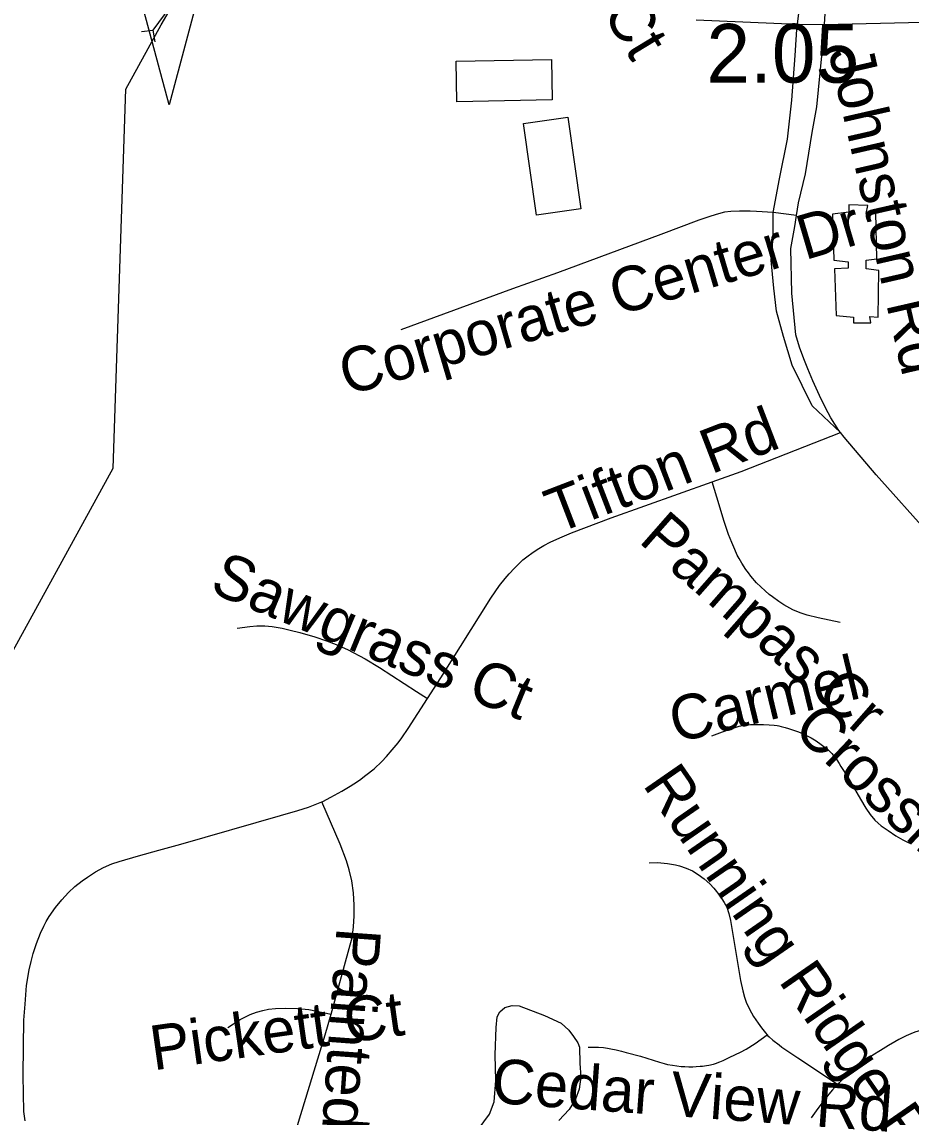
# Model space of a CAD drawing. Extents: x 1383679 to 1536984, y 460658 to 651027.
# Drawn here: x 1444051 to 1445945, y 489649 to 491982 of the extents above; entities that cross this region are included whole.
import ezdxf

# ---------------------------------------------------------------- set-up
doc = ezdxf.new("R2010")
doc.units = 0
for name, color, linetype in [('Exist Cultural Warehouse Building Footprint', 7, 'Continuous'), ('Exist Hydrographic Creek Single Shore', 7, 'Continuous'), ('Exist Road Non-System Type 51', 7, 'Continuous'), ('Exist Road Non-System Type 51 Label', 7, 'Continuous'), ('Exist Road Primary NC UnDivided 4 Lane Attributed', 7, 'Continuous'), ('Exist Road Secondary Mileage Hundredths English Label', 7, 'Continuous'), ('Exist Road Secondary Structure Culvert Attributed CELL', 7, 'Continuous'), ('Exist Road Secondary Structure Culvert CELL', 7, 'Continuous')]:
    doc.layers.add(name, color=color, linetype=linetype)

msp = doc.modelspace()

# ---------------------------------------------------------------- linework, layer by layer
at = {"layer": 'Exist Cultural Warehouse Building Footprint'}
for points in [[(1445178.6, 491902), (1445180.2, 491815.7), (1444977, 491811.9), (1444975.4, 491898.2), (1445178.6, 491902)], [(1445119.4, 491765.3), (1445213.5, 491778.6), (1445241, 491583.7), (1445146.9, 491570.4), (1445119.4, 491765.3)], [(1445812.4, 491592.2), (1445812.4, 491576.7), (1445777.2, 491572), (1445780.4, 491474.2), (1445810.8, 491471.1), (1445810.8, 491457.2), (1445782, 491455.6), (1445785.2, 491356.2), (1445822, 491353.1), (1445822, 491340.7), (1445858.8, 491340.7), (1445857.2, 491354.7), (1445874.8, 491353.1), (1445876.4, 491452.5), (1445849.2, 491455.6), (1445849.2, 491474.2), (1445871.6, 491477.3), (1445870, 491576.7), (1445849.2, 491573.6), (1445852.4, 491590.7), (1445812.4, 491592.2)]]:
    msp.add_lwpolyline(points, dxfattribs=at)
at = {"layer": 'Exist Hydrographic Creek Single Shore'}
msp.add_lwpolyline([(1443490.2, 489395.8), (1443517.3, 489946.6), (1443570.2, 490119.5), (1443673.2, 490275), (1443995.2, 490577.1), (1444245.2, 491031.6), (1444272.1, 491838.8), (1444347.5, 491975.6), (1444364.1, 492005), (1444375.6, 492029.3), (1444402.4, 492070.2), (1444764, 492263.2), (1445089, 492499.4), (1445408, 492730.5), (1445453.8, 492777.2), (1445478, 492822.8), (1445503.4, 492907.1), (1445567.9, 493066.2), (1445627.6, 493256.8)], dxfattribs=at)
at = {"layer": 'Exist Road Non-System Type 51'}
for p, q in [((1445705.3, 492000.5), (1445702.4, 491977.2)), ((1445761.2, 491999.8), (1445759.6, 491976.3)), ((1445697.8, 491910.3), (1445702.4, 491977.2)), ((1445759.6, 491976.3), (1445755, 491909.6)), ((1445700.7, 491569.7), (1445650.8, 491575.6))]:
    msp.add_line(p, q, dxfattribs=at)
for points in [[(1445650.8, 491575.6), (1445664.7, 491647.3), (1445681.5, 491732), (1445690.8, 491815), (1445697.8, 491910.3)], [(1445700.7, 491569.7), (1445704.7, 491596.8), (1445719.6, 491658.1), (1445734.4, 491746.5), (1445743.7, 491800.6), (1445755, 491909.6)], [(1445650.8, 491575.6), (1445615.3, 491578.2), (1445602.3, 491578.6), (1445579, 491579), (1445560.9, 491578.2), (1445547.1, 491576.3), (1445534.8, 491573.1), (1445518.3, 491568.4), (1445492.6, 491559.3), (1445411.5, 491528.7), (1445191.4, 491447.3), (1445096, 491413), (1444858.2, 491326.2)], [(1445794.3, 491107.2), (1445734.4, 491164.1), (1445691.7, 491250.7), (1445673.1, 491312), (1445658.2, 491366), (1445652.7, 491414.7), (1445647.1, 491474.2), (1445650.8, 491522.9), (1445650.8, 491575.6)], [(1445794.3, 491107.2), (1445791.2, 491111.4), (1445782.1, 491124.8), (1445774.2, 491138.4), (1445762.6, 491159.9), (1445749.6, 491186.1), (1445735.7, 491217.3), (1445724.7, 491243.2), (1445716.3, 491264.3), (1445707.3, 491289.1), (1445699.2, 491315.4), (1445690.8, 491403.9), (1445688.9, 491499.5), (1445697.3, 491546.3), (1445700.7, 491569.7)], [(1445521.2, 491002.2), (1445582.7, 491024), (1445794.3, 491107.2)], [(1446134.7, 490647.2), (1446134.6, 490647.5), (1446128.8, 490665.1), (1446118.9, 490689.6), (1446104.6, 490720.6), (1446086.1, 490755.1), (1446071.5, 490780), (1446053.8, 490807), (1446040.6, 490824.4), (1446025.6, 490843.6), (1445984.9, 490889.3), (1445870.7, 491016.9), (1445802, 491097.2), (1445794.3, 491107.2)], [(1444914.8, 490541), (1444942.9, 490584.9), (1445049.8, 490754.8), (1445058.8, 490767.9), (1445067.8, 490781.2), (1445079.8, 490796.6), (1445088.3, 490806.2), (1445099.8, 490818.4), (1445107.7, 490826.3), (1445118, 490835.9), (1445129, 490844.8), (1445137.1, 490850.6), (1445148.5, 490858.1), (1445162.5, 490866.7), (1445176.2, 490874), (1445196.6, 490883), (1445221.3, 490893.5), (1445305.9, 490925.9), (1445521.2, 491002.2)], [(1445793.9, 490703), (1445747.2, 490712.6), (1445723.6, 490718.1), (1445708.4, 490723.4), (1445693, 490729.9), (1445673.5, 490740.4), (1445662.8, 490747.7), (1445649.4, 490757.6), (1445642.7, 490762.6), (1445634.1, 490770), (1445615.7, 490787.3), (1445603.3, 490801.7), (1445598.2, 490808.2), (1445592.6, 490815.7), (1445584.5, 490828.9), (1445578.3, 490839.3), (1445574.6, 490846.4), (1445569.2, 490858.2), (1445562.7, 490873), (1445555.8, 490890.4), (1445545.9, 490919.6), (1445535.9, 490953.4), (1445521.2, 491002.2)], [(1444509.5, 490690.8), (1444536, 490694.4), (1444551.3, 490695.6), (1444568, 490695.6), (1444583.6, 490694.4), (1444605.2, 490690.5), (1444622, 490686.4), (1444643, 490681.1), (1444674.4, 490671.9), (1444699.8, 490663.4), (1444720.3, 490655.5), (1444744.4, 490645.2), (1444782.1, 490625.1), (1444812.6, 490606.8), (1444891, 490555.4), (1444914.8, 490541)], [(1444689.3, 490320.7), (1444691.4, 490321.5), (1444709.1, 490330.7), (1444732.4, 490343.3), (1444750.1, 490354), (1444758, 490358.9), (1444769.5, 490367), (1444783.3, 490377.2), (1444800.8, 490390.9), (1444817.2, 490406.8), (1444827, 490417.4), (1444839.7, 490431.2), (1444851.9, 490446.2), (1444859.8, 490457.2), (1444873.4, 490476.7), (1444914.8, 490541)], [(1445520.5, 490461.2), (1445543.4, 490469.5), (1445559.2, 490475.2), (1445569.9, 490479.1), (1445578.8, 490481.8), (1445589.9, 490483.8), (1445602.7, 490485.2), (1445616.5, 490485.7), (1445630.5, 490485.4), (1445642.2, 490484.9), (1445652.9, 490483.9), (1445659.4, 490483), (1445663.1, 490482.3), (1445667.8, 490481.3), (1445676.5, 490479), (1445684, 490477), (1445692.1, 490474.4), (1445702.8, 490470.7), (1445712, 490466.9), (1445719.5, 490463.5), (1445731.7, 490457.1), (1445742.4, 490450.8), (1445753.6, 490443.2), (1445766.9, 490432.6), (1445775.9, 490423.9), (1445781.1, 490417.5), (1445786.3, 490410.3), (1445791.5, 490402.2), (1445795.5, 490396.2), (1445807.6, 490377.1), (1445837.1, 490326.5), (1445848.5, 490307.4), (1445857.4, 490293.8), (1445867.3, 490282), (1445874.4, 490275.2), (1445881, 490269.7), (1445895.7, 490259.6), (1445912.4, 490248.6), (1445926.9, 490240), (1445935.6, 490235.4), (1445944.8, 490231.3)], [(1444057.7, 489641.6), (1444054.5, 489661.5), (1444053.1, 489738.2), (1444053.8, 489799.6), (1444055, 489855.8), (1444057.7, 489889.8), (1444060.6, 489929.4), (1444065.8, 489963.3), (1444070.3, 489980.6), (1444075, 489998), (1444081.9, 490018.9), (1444090.3, 490041.4), (1444097.2, 490056), (1444102.1, 490066.2), (1444108.4, 490076.7), (1444122.3, 490096), (1444135.8, 490112.2), (1444150.2, 490127.6), (1444163.7, 490140.1), (1444179, 490152.6), (1444190.2, 490160.5), (1444207.4, 490171.7), (1444224.6, 490181), (1444242, 490188.4), (1444257.5, 490193.9), (1444298.9, 490205.6), (1444342.6, 490217.7), (1444389, 490230.3), (1444601.4, 490291.3), (1444638.1, 490302.5), (1444661.1, 490309.7), (1444689.3, 490320.7)], [(1444709.2, 489868.5), (1444750.1, 490015.9), (1444754, 490031.2), (1444757, 490054.4), (1444758.7, 490077.8), (1444758.6, 490100.9), (1444757.2, 490126.9), (1444753.3, 490152.5), (1444747.9, 490175.6), (1444741.9, 490194.8), (1444728.4, 490230.4), (1444689.3, 490320.7)], [(1445386.8, 490191.1), (1445404.3, 490191.3), (1445425.9, 490189.2), (1445442.7, 490186.6), (1445451.6, 490184.5), (1445465.8, 490179.8), (1445479, 490174), (1445491.1, 490166.1), (1445504.2, 490156.7), (1445515.8, 490146.1), (1445524.7, 490137.2), (1445538.3, 490120.1), (1445546.8, 490106.7), (1445552.1, 490096.2), (1445556.3, 490083.1), (1445559.8, 490067.9), (1445578.3, 489957.4), (1445581.5, 489940.1), (1445586.2, 489918), (1445589.9, 489904.9), (1445593.6, 489894.4), (1445600.4, 489879.1), (1445609.4, 489863.9), (1445618.8, 489849.7), (1445626.3, 489839.5), (1445634.5, 489828.5), (1445638.3, 489824.2)], [(1446202.3, 489904.6), (1446058.2, 489861.3), (1445995.3, 489843.2), (1445982.8, 489839.4), (1445968.5, 489835.2), (1445959.8, 489832.4), (1445952.9, 489830), (1445944.1, 489826.5), (1445934.2, 489822.4), (1445925.7, 489818.1), (1445918.4, 489814.3), (1445910.4, 489809.8), (1445896.8, 489802.1), (1445879.5, 489791), (1445863, 489780.9), (1445848.2, 489770.3), (1445835.1, 489760.2), (1445820.2, 489748), (1445805.6, 489735.5), (1445798.9, 489729.6), (1445790, 489721), (1445788.4, 489719.3)], [(1444489.1, 489840.1), (1444515.9, 489857.1), (1444536.7, 489867.6), (1444550.4, 489872.7), (1444563.6, 489876.4), (1444575.8, 489879.1), (1444591.2, 489880.8), (1444612.2, 489881.3), (1444637.6, 489880.8), (1444661.6, 489878.6), (1444709.2, 489868.5)], [(1445010.8, 489606.3), (1445046.5, 489655.9), (1445056.6, 489682.2), (1445060.4, 489727.4), (1445058.9, 489782.3), (1445061.1, 489840.2), (1445063.4, 489862.8), (1445068.6, 489873.3), (1445079.2, 489883.1), (1445095, 489886.8), (1445110, 489886.1), (1445163.9, 489865.4), (1445199.1, 489849.6), (1445215.4, 489834.2), (1445225.8, 489821.2), (1445235.1, 489807.8), (1445238.6, 489798.5)], [(1444609.1, 489477.5), (1444608.8, 489479.5), (1444608.1, 489493.2), (1444608.8, 489508.6), (1444610.2, 489521.5), (1444612.7, 489535.6), (1444616.3, 489553.1), (1444621.4, 489572.9), (1444628.2, 489597.7), (1444640, 489638.2), (1444696.9, 489824.2), (1444709.2, 489868.5)], [(1445257.1, 489798.2), (1445268.1, 489798.6), (1445278.6, 489798.5), (1445289.4, 489797.3), (1445298.4, 489796), (1445305.1, 489794.9), (1445316.3, 489792.7), (1445328, 489789.9), (1445338.2, 489787.1), (1445368.6, 489778.8), (1445395.3, 489770.7), (1445409.2, 489766.4), (1445418.7, 489763.6), (1445426, 489761.7), (1445436.4, 489759.7), (1445445.9, 489758.2), (1445455.1, 489757.4), (1445462.9, 489756.9), (1445471.5, 489756.5), (1445479.7, 489756.5), (1445487, 489756.9), (1445495.4, 489757.6), (1445500.6, 489758), (1445509.2, 489759.3), (1445513.9, 489760), (1445523.7, 489762.3), (1445528.4, 489763.8), (1445537.6, 489767.1), (1445544.6, 489770.1), (1445559, 489776.8), (1445581.2, 489787.5), (1445593.3, 489794.2), (1445612.9, 489806.3), (1445638.3, 489824.2)], [(1445638.3, 489824.2), (1445639.6, 489822.7), (1445642.5, 489820), (1445650.5, 489813.4), (1445663.6, 489803.2), (1445669.8, 489798.5), (1445703.2, 489775.7), (1445788.4, 489719.3)], [(1445238.6, 489798.5), (1445239.4, 489763.5), (1445241.6, 489734.9), (1445237.9, 489708.6), (1445229.6, 489687.5), (1445216.1, 489665.8), (1445194.2, 489642.4)], [(1445788.4, 489719.3), (1445783.7, 489714.2), (1445777.4, 489707.4), (1445769.7, 489697.9), (1445765.3, 489692.5), (1445759.6, 489685.1), (1445746.3, 489667.6), (1445732.2, 489647.9)]]:
    msp.add_lwpolyline(points, dxfattribs=at)
at = {"layer": 'Exist Road Primary NC UnDivided 4 Lane Attributed'}
msp.add_lwpolyline([(1445486.9, 491986), (1445702.4, 491977.2), (1445759.6, 491976.3), (1445968.8, 491981), (1446235.2, 491975.4), (1446313.3, 491980.2), (1446364.2, 491977.5), (1446825.6, 491978), (1447208.6, 491971.6), (1447596.6, 491974.1), (1447846.7, 491976), (1448007.8, 491975.1)], dxfattribs=at)
at = {"layer": 'Exist Road Secondary Structure Culvert Attributed CELL'}
msp.add_lwpolyline([(1444467.6, 492191.4), (1444364.1, 491805), (1444260.6, 492191.4), (1444364.1, 492005)], close=True, dxfattribs=at)
at = {"layer": 'Exist Road Secondary Structure Culvert CELL'}
for p, q in [((1444330.3, 491964.5), (1444366.6, 492012.9)), ((1444305.1, 491961.5), (1444330.3, 491964.5)), ((1444334.6, 491939.4), (1444330.3, 491964.5))]:
    msp.add_line(p, q, dxfattribs=at)

# ---------------------------------------------------------------- texts
at = {"layer": 'Exist Road Non-System Type 51 Label'}
for s, rotation, p in [('Nellum Ct', 301.2703, (1445062.2, 492370.7)), ('Johnston Rd', 282.885, (1445768.6, 491918.9)), ('Corporate Center Dr', 16.4922, (1444743.5, 491185.4)), ('Tifton Rd', 21.0381, (1445189.3, 490891.1)), ('Pampas Cr', 318.7019, (1445362.1, 490874.8)), ('Sawgrass Ct', 337.5681, (1444447.6, 490768.7)), ('Carmel', 13.6277, (1445443.2, 490445.8)), ('Crossing', 316.4925, (1445689.8, 490471.8)), ('Running Ridge Rd', 304.6958, (1445371.4, 490357.4)), ('Painted Tree Rd', 265.8606, (1444721.2, 490054.8)), ('Pickett Ct', 8.049, (1444330.8, 489748.6)), ('Cedar View Rd', 355.822, (1445049.4, 489680))]:
    msp.add_text(s, height=95, rotation=rotation, dxfattribs=at).set_placement(p)
at = {"layer": 'Exist Road Secondary Mileage Hundredths English Label'}
msp.add_text('2.05', height=125, rotation=359.9999, dxfattribs=at).set_placement((1445508.9, 491852.4))

doc.saveas('drawing.dxf')
